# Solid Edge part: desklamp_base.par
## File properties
Author: adamb
Template: Iso Metric Part.par
Last saved by: adamb
Revision: 6
Application: Solid Edge
Username: adamb
Dokumentum tartalom típus: 0
Sűrűség: 0,000 kg/m^3
Pontosság: 0,990
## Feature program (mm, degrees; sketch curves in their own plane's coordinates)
sketch for "unnamed RevolvedProtrusion 1" plane through (0, 0, 0) normal (0, -1, 0) x-axis (1, 0, 0)
  arc centre (0, 0) radius 37.5 from (0, -37.5) to (37.5, 0) ccw
  line (0, 35) -> (13.4629, 35)
revolve "unnamed RevolvedProtrusion 1" add full turn 360 deg about sketch line (0, 35) -> (0, -37.5)
sketch for "unnamed Protrusion 1" #1 plane through (0, 0, 0) normal (0, 0, 1) x-axis (1, 0, 0)
  circle centre (15, 15) radius 4
sketch for "unnamed Protrusion 1" #2 plane through (0, 0, 0) normal (0, 0, 1) x-axis (1, 0, 0)
  circle centre (15, -15) radius 4
sketch for "unnamed Protrusion 1" #3 plane through (0, 0, 0) normal (0, 0, 1) x-axis (1, 0, 0)
  circle centre (-15, -15) radius 4
sketch for "unnamed Protrusion 1" #4 plane through (0, 0, 0) normal (0, 0, 1) x-axis (1, 0, 0)
  circle centre (-15, 15) radius 4
extrude "unnamed Protrusion 1" add finite 37.5 along -normal
sketch for "unnamed Cutout 1" plane through (0, 0, 35) normal (0, 0, 1) x-axis (0, 1, 0)
extrude "unnamed Cutout 1" cut finite 10 along -normal
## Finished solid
Body 1: solid body, 12 faces, 11 edges, 0 vertices.
  Faces by surface: plane 6, cylinder 5, sphere 1
  Edges by curve: circle 7, intersection 4
Bounding box of the edges (mm; curved faces can reach further): 38.000 x 38.000 x 72.500, from (-19, -19, -37.5) to (19, 19, 35).
Cylindrical faces by radius (mm): R4 x5
Spherical faces by radius (mm): R37.5 x1
Planar faces by outward normal: +z 2, -z 4
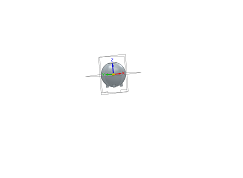
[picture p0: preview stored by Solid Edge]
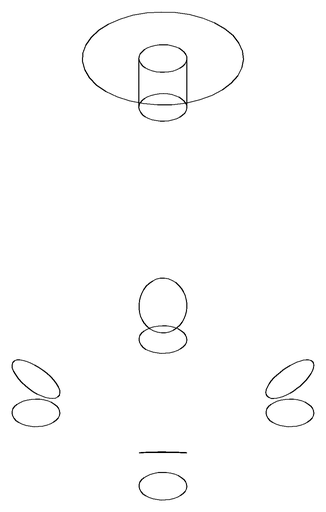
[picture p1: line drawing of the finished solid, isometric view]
